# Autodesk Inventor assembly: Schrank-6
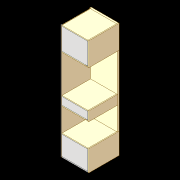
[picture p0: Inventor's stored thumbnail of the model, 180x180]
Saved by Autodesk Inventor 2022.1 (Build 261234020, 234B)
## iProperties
Created: 2022-03
Part Number: Schrank-6
Document SubType Name: Assembly
Designer: Ruhl
Author: Ruhl
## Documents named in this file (2)
- Z:\INVENTOR\FORUM UND TEST\VOLUMENKÖRPER VERSCHMELZEN\Schrank-6.iam
- Z:\INVENTOR\FORUM UND TEST\VOLUMENKÖRPER VERSCHMELZEN\Korpus-6.ipt
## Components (1 placed, 1 different names)
1. Korpus-6:1
